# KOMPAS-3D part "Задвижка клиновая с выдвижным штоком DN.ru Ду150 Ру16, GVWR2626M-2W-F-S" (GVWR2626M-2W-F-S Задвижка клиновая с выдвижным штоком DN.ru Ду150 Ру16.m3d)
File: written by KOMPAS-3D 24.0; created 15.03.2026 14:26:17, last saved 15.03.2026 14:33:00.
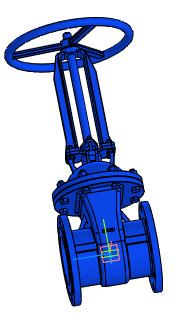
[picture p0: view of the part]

Document properties: Автор: R2D2; Полное имя файла: GVWR2626M-2W-F-S Задвижка клиновая с выдвижным штоком DN.ru Ду150 Ру16.cdw

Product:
- Part/product: Задвижка клиновая с выдвижным штоком DN.ru Ду150 Ру16  | designation GVWR2626M-2W-F-S
    Масса: 67
    Раздел спецификации: Прочие изделия
    Форматы листов документа: A2
    Примечание: D040-10504
    additional columns: D040-10504

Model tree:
1. Операция без истории:1

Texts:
  GVWR2626M-2W-F-S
